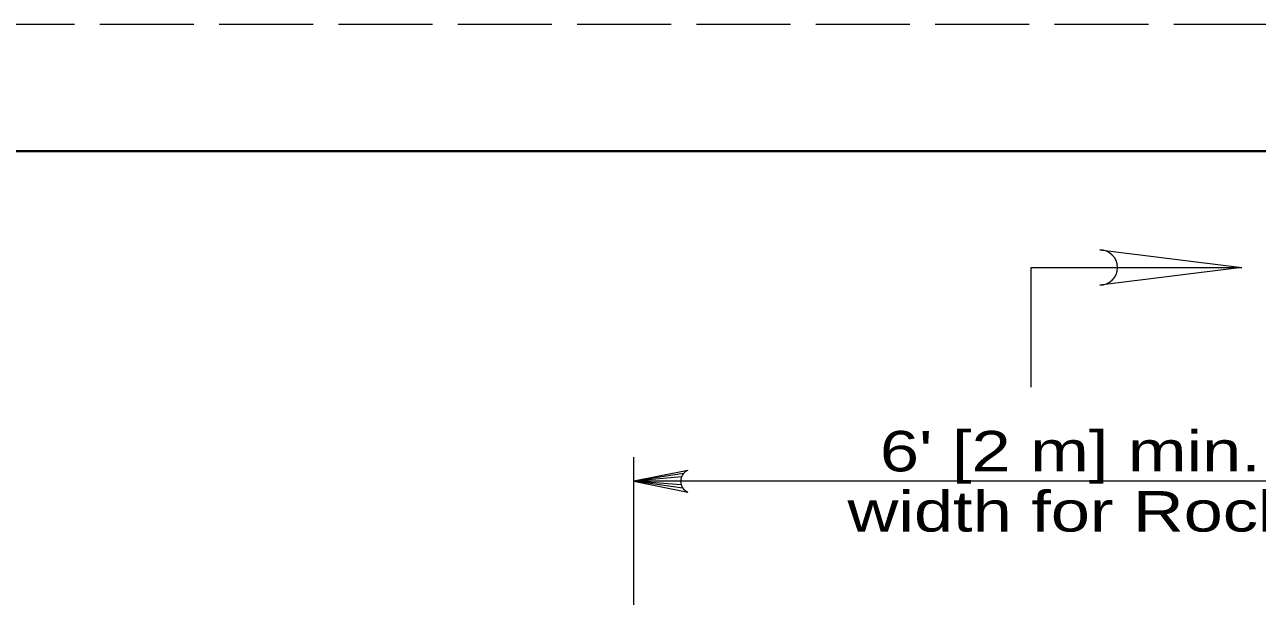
# Model space of a CAD drawing. Extents: x 1083.1 to 1117.1, y 672.5 to 716.5.
# Drawn here: x 1089.081 to 1093.956, y 714.248 to 716.508 of the extents above; entities that cross this region are included whole.
import ezdxf
from ezdxf.enums import TextEntityAlignment as Align

# ---------------------------------------------------------------- set-up
doc = ezdxf.new("R2010")
doc.units = 0
doc.header["$LTSCALE"] = 0.062
doc.linetypes.add('LONG_DASHED', pattern=[7.5, 6, -1.5])
doc.layers.add('1', color=7, linetype='Continuous', lineweight=13)
doc.layers.add('47', color=7, linetype='Continuous', lineweight=13)

msp = doc.modelspace()

# ---------------------------------------------------------------- linework, layer by layer
at = {"layer": '1', "lineweight": 25}
msp.add_line((1085.12642, 716.00825), (1116.62642, 716.00825), dxfattribs=at)
at = {"layer": '1'}
for p, q in [((1091.49067, 713.0395), (1091.49067, 714.79783)), ((1091.6865, 714.73283), (1091.49067, 714.70292)), ((1091.67908, 714.72033), (1091.49067, 714.70292)), ((1094.89058, 714.70292), (1091.49067, 714.70292)), ((1091.67567, 714.70292), (1091.49067, 714.70292)), ((1091.67767, 714.68925), (1091.49067, 714.70292)), ((1091.68417, 714.67583), (1091.49067, 714.70292)), ((1091.66908, 714.70292), (1091.49333, 714.70292))]:
    msp.add_line(p, q, dxfattribs=at)
at = {"layer": '1', "linetype": 'LONG_DASHED'}
msp.add_lwpolyline([(1083.12642, 694.50825), (1117.12642, 694.50825), (1117.12642, 716.50825), (1083.12642, 716.50825)], close=True, dxfattribs=at)
at = {"layer": '1', "lineweight": 40}
msp.add_lwpolyline([(1085.12642, 716.00825), (1116.62642, 716.00825), (1116.62642, 695.00825), (1085.12642, 695.00825)], close=True, dxfattribs=at)
msp.add_lwpolyline([(1085.12642, 716.00825), (1116.62642, 716.00825), (1116.62642, 695.00825), (1085.12642, 695.00825)], close=True, dxfattribs=at)
at = {"layer": '1'}
for points in [[(1093.06208, 715.07492), (1093.06208, 715.54775), (1093.8955, 715.54775)], [(1091.70442, 714.74567), (1091.49067, 714.70292), (1091.70442, 714.66017)]]:
    msp.add_lwpolyline(points, dxfattribs=at)
msp.add_arc((1091.72169, 714.70285), 0.04613, 112.08605, 247.91218, dxfattribs=at)
at = {"layer": '47'}
msp.add_lwpolyline([(1093.333, 715.618), (1093.8955, 715.54775), (1093.333, 715.4775)], dxfattribs=at)
msp.add_arc((1093.33298, 715.54773), 0.07025, 270, 90, dxfattribs=at)

# ---------------------------------------------------------------- texts
at = {"layer": '1', "width": 1.3}
for s, p in [("6' [2 m] min.", (1093.21692, 714.74183)), ('width for Rock', (1093.21692, 714.50383))]:
    msp.add_text(s, height=0.16, dxfattribs=at).set_placement(p, align=Align.CENTER)

doc.saveas('drawing.dxf')
